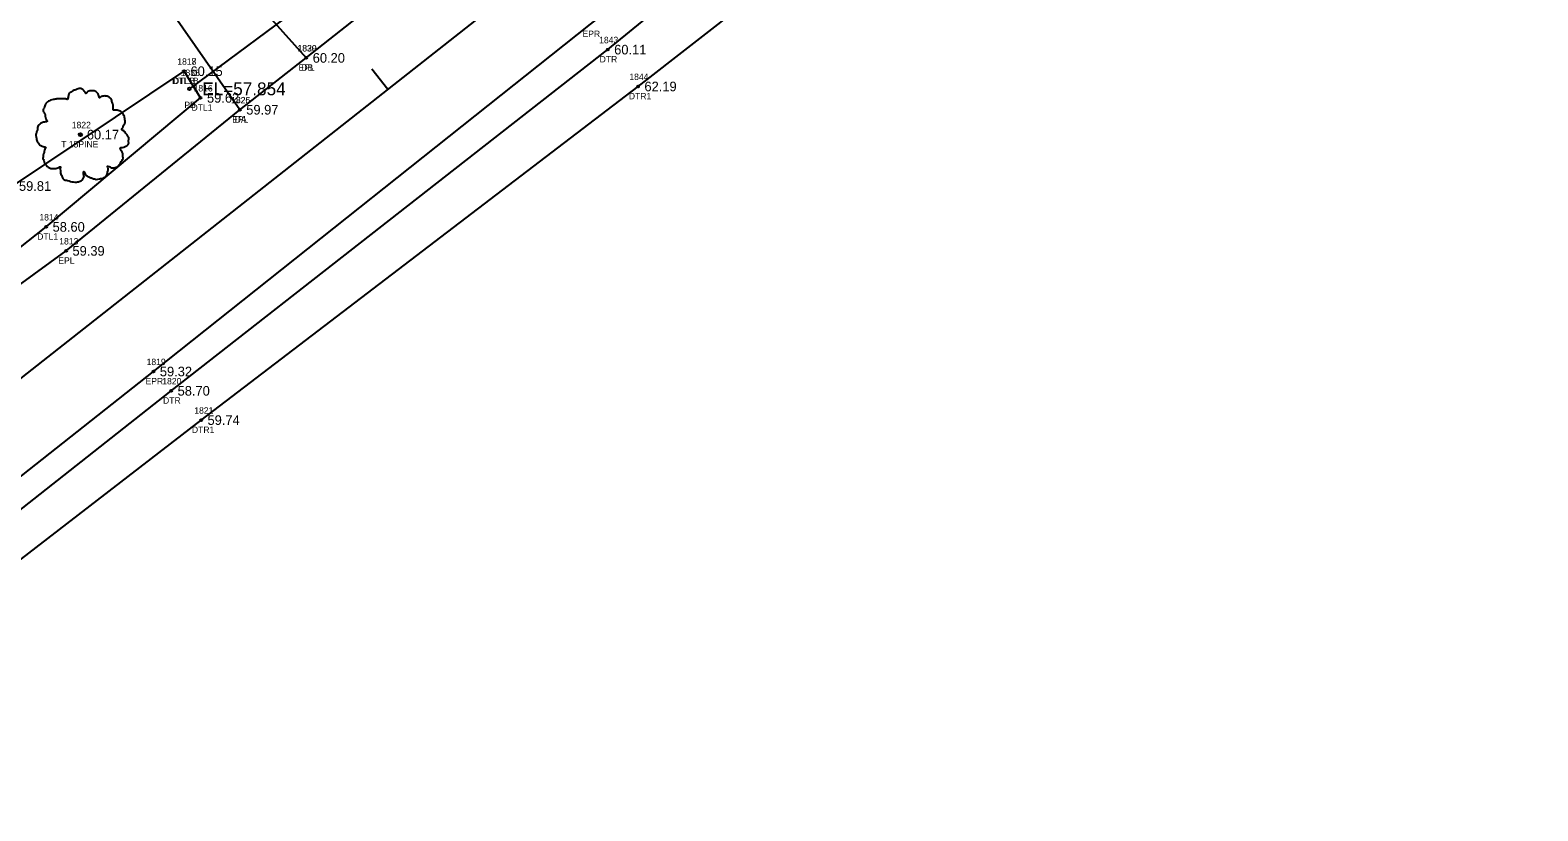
# Model space of a CAD drawing. Extents: x 2420113 to 2422887, y 845323 to 846653.
# Drawn here: x 2422429.8 to 2422664.8, y 846237.5 to 846359.2 of the extents above; entities that cross this region are included whole.
import ezdxf

# ---------------------------------------------------------------- set-up
doc = ezdxf.new("R2010")
doc.units = 0
for name, color, linetype in [('RD_EX_DR_Pipe', 7, 'Continuous'), ('RD_EX_DR_Pipe_txCode', 7, 'Continuous'), ('RD_EX_Driveway', 7, 'Continuous'), ('RD_EX_Driveway_txCode', 7, 'Continuous'), ('RD_EX_H2O', 7, 'Continuous'), ('RD_EX_H2O_txCode', 7, 'Continuous'), ('RD_EX_Road', 7, 'Continuous'), ('RD_EX_Road_txCode', 7, 'Continuous'), ('RD_EX_TX_Driveway_ELEV', 7, 'Continuous'), ('RD_EX_TX_H2O_ELEV', 7, 'Continuous'), ('RD_EX_TX_Road_ELEV', 7, 'Continuous'), ('RD_EX_TX_VEG_ELEV', 7, 'Continuous'), ('RD_EX_VEG', 7, 'Continuous'), ('RD_EX_VEG_txCode', 7, 'Continuous'), ('RD_HC_Cl', 7, 'Continuous'), ('RD_HC_Data_Tic', 7, 'Continuous'), ('RD_SMD_Locator', 7, 'Continuous'), ('RD_TX_Pipe_ElevEX', 7, 'Continuous')]:
    doc.layers.add(name, color=color, linetype=linetype)

msp = doc.modelspace()

# ---------------------------------------------------------------- linework, layer by layer
at = {"layer": 'RD_EX_DR_Pipe'}
msp.add_line((2422474.67, 846364.92), (2422454.62, 846350.03), dxfattribs=at)
at = {"layer": 'RD_EX_Driveway'}
for p, q in [((2422454.42, 846375.46), (2422472.85, 846354.85)), ((2422462.49, 846346.77), (2422449.78, 846364.98))]:
    msp.add_line(p, q, dxfattribs=at)
at = {"layer": 'RD_EX_H2O'}
for points in [[(2422383.12, 846248.84), (2422451.79, 846302.96), (2422519.84, 846356.14), (2422594.22, 846416.85), (2422660.96, 846466.59)], [(2422383.12, 846248.84), (2422386.53, 846244.46), (2422456.45, 846298.4), (2422524.56, 846350.4), (2422601.29, 846410.12), (2422664.82, 846461.69)], [(2422410.35, 846320.94), (2422427.06, 846334.88), (2422453.8, 846352.78)], [(2422410.35, 846320.94), (2422411.83, 846316.92), (2422415.48, 846315.23), (2422432.3, 846328.51), (2422456.37, 846348.62), (2422453.8, 846352.78)]]:
    msp.add_lwpolyline(points, dxfattribs=at)
at = {"layer": 'RD_EX_Road'}
for points in [[(2421810.77, 845819.82), (2421809.69, 845832.82), (2421803.88, 845842.86), (2421852.96, 845873.69), (2421939.48, 845935.12), (2421980.78, 845967.01), (2422140.12, 846092.81), (2422210.03, 846148.43), (2422282.88, 846205.21), (2422291.79, 846212.09), (2422354.49, 846261.98), (2422400.82, 846297.88), (2422417.34, 846311.65), (2422435.4, 846324.77), (2422462.49, 846346.77), (2422472.85, 846354.85), (2422502.3, 846378.16), (2422578.05, 846437.54), (2422605.64, 846459.09), (2422626.64, 846476.17), (2422642.61, 846488.86)], [(2421810.77, 845819.82), (2421865.31, 845853.52), (2421953.26, 845916.07), (2421995.06, 845948.03), (2422068.36, 846005.98), (2422153.46, 846073.36), (2422229.55, 846134.03), (2422245.4, 846145.63), (2422297.08, 846186.88), (2422369.77, 846243.69), (2422382.04, 846253.08), (2422449.02, 846305.97), (2422517.14, 846360.1), (2422592.58, 846419.1), (2422657.51, 846470.1)]]:
    msp.add_lwpolyline(points, dxfattribs=at)
at = {"layer": 'RD_EX_VEG'}
for centre, radius in [((2422437.64, 846342.89), 0.25), ((2422437.63, 846342.87), 0.0001)]:
    msp.add_circle(centre, radius, dxfattribs=at)
for points in [[(2422437.77, 846350.06), (2422437.47, 846350.08), (2422437.15, 846349.98), (2422436.9, 846349.88), (2422436.67, 846349.81), (2422436.45, 846349.71), (2422436.15, 846349.53), (2422435.92, 846349.33), (2422435.8, 846349.08), (2422435.75, 846348.86), (2422435.7, 846348.59), (2422435.7, 846348.41), (2422435.57, 846348.39), (2422435.42, 846348.41), (2422435.17, 846348.49), (2422434.92, 846348.49), (2422434.67, 846348.49), (2422434.32, 846348.46), (2422433.97, 846348.46), (2422433.7, 846348.41), (2422433.37, 846348.36), (2422433, 846348.24), (2422432.65, 846348.11), (2422432.35, 846347.86), (2422432.1, 846347.39), (2422431.97, 846347.04), (2422431.82, 846346.79), (2422431.97, 846346.34), (2422432.15, 846345.99), (2422432.17, 846345.79), (2422432.25, 846345.36), (2422432.35, 846345.14), (2422432.47, 846344.94), (2422432.4, 846344.91), (2422432.02, 846344.86), (2422431.72, 846344.76), (2422431.3, 846344.54), (2422431.07, 846344.31), (2422430.97, 846343.99), (2422430.95, 846343.64), (2422430.85, 846343.44), (2422430.77, 846343.16), (2422430.75, 846343.09), (2422430.7, 846342.76), (2422430.8, 846342.31), (2422430.82, 846341.96), (2422430.95, 846341.74), (2422431.1, 846341.56), (2422431.27, 846341.31), (2422431.67, 846341.09), (2422432, 846340.99), (2422432.2, 846340.96), (2422432.02, 846340.46), (2422431.97, 846340.11), (2422431.85, 846339.71), (2422431.85, 846339.64), (2422431.8, 846339.16), (2422431.95, 846338.84), (2422432.02, 846338.46), (2422432.2, 846338.24), (2422432.47, 846337.94), (2422432.8, 846337.71), (2422433.3, 846337.59), (2422433.7, 846337.61), (2422434.27, 846337.79), (2422434.52, 846337.86), (2422434.5, 846337.69), (2422434.52, 846337.31), (2422434.52, 846336.89), (2422434.67, 846336.57), (2422434.77, 846336.29), (2422434.92, 846336.04), (2422435.25, 846335.82), (2422435.65, 846335.74), (2422436.07, 846335.59), (2422436.52, 846335.52), (2422437.02, 846335.49), (2422437.62, 846335.64), (2422437.9, 846335.77), (2422438, 846335.94), (2422438.2, 846336.32), (2422438.15, 846336.54), (2422438.17, 846337.14), (2422438.27, 846336.97), (2422438.45, 846336.62), (2422438.95, 846336.32), (2422439.35, 846336.14), (2422439.82, 846335.99), (2422440.12, 846335.92), (2422440.6, 846335.99), (2422440.97, 846336.07), (2422441.35, 846336.19), (2422441.65, 846336.47), (2422441.82, 846336.74), (2422441.87, 846337.02), (2422441.94, 846337.39), (2422441.99, 846337.56)], [(2422441.99, 846337.56), (2422441.92, 846337.74), (2422441.87, 846337.99), (2422441.94, 846337.96), (2422442.12, 846337.91), (2422442.39, 846337.79), (2422442.62, 846337.71), (2422442.94, 846337.74), (2422443.22, 846337.84), (2422443.67, 846338.11), (2422443.94, 846338.59), (2422444.22, 846338.99), (2422444.29, 846339.31), (2422444.24, 846339.54), (2422444.22, 846340.04), (2422444.02, 846340.29), (2422443.97, 846340.41), (2422443.87, 846340.81), (2422443.94, 846340.86), (2422444.22, 846340.91), (2422444.59, 846341.04), (2422444.87, 846341.16), (2422445.09, 846341.34), (2422445.17, 846341.56), (2422445.14, 846341.96), (2422445.19, 846342.36), (2422445.12, 846342.51), (2422445.02, 846342.66), (2422444.94, 846342.86), (2422444.79, 846343.01), (2422444.69, 846343.16), (2422444.59, 846343.26), (2422444.47, 846343.41), (2422444.29, 846343.54), (2422444.14, 846343.59), (2422444.09, 846343.74), (2422444.24, 846343.94), (2422444.29, 846344.04), (2422444.32, 846344.26), (2422444.54, 846344.61), (2422444.59, 846345.01), (2422444.54, 846345.44), (2422444.49, 846345.71), (2422444.34, 846345.99), (2422444.14, 846346.24), (2422444.02, 846346.41), (2422443.84, 846346.54), (2422443.52, 846346.66), (2422443.27, 846346.71), (2422442.92, 846346.71), (2422442.72, 846346.76), (2422442.74, 846346.81), (2422442.74, 846346.96), (2422442.74, 846347.24), (2422442.67, 846347.69), (2422442.52, 846348.19), (2422442.52, 846348.21), (2422442.42, 846348.46), (2422442.19, 846348.66), (2422442.02, 846348.76), (2422441.82, 846348.88), (2422441.57, 846348.91), (2422441.27, 846348.91), (2422441, 846348.86), (2422440.8, 846348.76), (2422440.62, 846348.63), (2422440.55, 846348.78), (2422440.45, 846349.08), (2422440.4, 846349.23), (2422440.25, 846349.41), (2422440.02, 846349.61), (2422439.57, 846349.73), (2422438.95, 846349.66), (2422438.65, 846349.46), (2422438.5, 846349.28), (2422438.45, 846349.41), (2422438.25, 846349.61), (2422438.15, 846349.78), (2422437.97, 846349.91), (2422437.82, 846350.01), (2422437.72, 846350.06)]]:
    msp.add_spline(points, degree=3, dxfattribs=at)
at = {"layer": 'RD_HC_Cl'}
msp.add_line((2421944.32, 845923.85), (2422642.7, 846473.66), dxfattribs=at)
at = {"layer": 'RD_HC_Data_Tic'}
msp.add_line((2422485.55, 846349.94), (2422483.08, 846353.08), dxfattribs=at)
at = {"layer": 'RD_SMD_Locator'}
for centre, radius in [((2422519.84, 846356.14), 0.15), ((2422472.85, 846354.85), 0.15), ((2422472.85, 846354.85), 0.15), ((2422453.8, 846352.78), 0.15), ((2422453.8, 846352.78), 0.15), ((2422454.62, 846350.03), 0.2), ((2422456.37, 846348.62), 0.15), ((2422524.56, 846350.4), 0.15), ((2422462.49, 846346.77), 0.15), ((2422462.49, 846346.77), 0.15), ((2422437.64, 846342.89), 0.15), ((2422432.3, 846328.51), 0.15), ((2422435.4, 846324.77), 0.15), ((2422449.02, 846305.97), 0.15), ((2422451.79, 846302.96), 0.15), ((2422456.45, 846298.4), 0.15)]:
    msp.add_circle(centre, radius, dxfattribs=at)

# ---------------------------------------------------------------- texts
at = {"layer": 'RD_EX_DR_Pipe_txCode'}
for s, p in [('1835', (2422453.28, 846352.03)), ('PB', (2422453.84, 846347.03))]:
    msp.add_text(s, height=1, dxfattribs=at).set_placement(p)
at = {"layer": 'RD_EX_Driveway_txCode'}
for s, p in [('1829', (2422471.5, 846355.85)), ('DB', (2422472.07, 846352.85)), ('1826', (2422461.12, 846347.77)), ('DA', (2422461.7, 846344.77))]:
    msp.add_text(s, height=1, dxfattribs=at).set_placement(p)
at = {"layer": 'RD_EX_H2O_txCode'}
for s, p in [('1843', (2422518.5, 846357.14)), ('1817', (2422452.74, 846353.78)), ('1818', (2422452.74, 846353.78)), ('DTR', (2422518.57, 846354.14)), ('DTL1B', (2422451.92, 846350.78)), ('DTLB', (2422452.08, 846350.78)), ('1844', (2422523.21, 846351.4)), ('1816', (2422455.28, 846349.62)), ('DTR1', (2422523.13, 846348.4)), ('DTL1', (2422454.96, 846346.62)), ('1814', (2422431.24, 846329.51)), ('DTL1', (2422430.9, 846326.51)), ('1820', (2422450.4, 846303.96)), ('DTR', (2422450.52, 846300.96)), ('1821', (2422455.39, 846299.4)), ('DTR1', (2422455.02, 846296.4))]:
    msp.add_text(s, height=1, dxfattribs=at).set_placement(p)
at = {"layer": 'RD_EX_Road_txCode'}
for s, p in [('EPR', (2422515.91, 846358.1)), ('1830', (2422471.46, 846355.85)), ('EPL', (2422471.64, 846352.85)), ('1825', (2422461.15, 846347.77)), ('EPL', (2422461.29, 846344.77)), ('1813', (2422434.34, 846325.77)), ('EPL', (2422434.19, 846322.77)), ('1819', (2422447.96, 846306.97)), ('EPR', (2422447.79, 846303.97))]:
    msp.add_text(s, height=1, dxfattribs=at).set_placement(p)
at = {"layer": 'RD_EX_TX_Driveway_ELEV'}
for s, p in [('60.20', (2422473.85, 846354.1)), ('59.97', (2422463.49, 846346.02))]:
    msp.add_text(s, height=1.5, dxfattribs=at).set_placement(p)
at = {"layer": 'RD_EX_TX_H2O_ELEV'}
for s, p in [('60.11', (2422520.84, 846355.39)), ('60.15', (2422454.8, 846352.03)), ('60.15', (2422454.8, 846352.03)), ('62.19', (2422525.56, 846349.65)), ('59.62', (2422457.37, 846347.87)), ('59.81', (2422428.06, 846334.13)), ('58.60', (2422433.3, 846327.76)), ('58.70', (2422452.79, 846302.21)), ('59.74', (2422457.45, 846297.65))]:
    msp.add_text(s, height=1.5, dxfattribs=at).set_placement(p)
at = {"layer": 'RD_EX_TX_Road_ELEV'}
for s, p in [('60.20', (2422473.85, 846354.1)), ('59.97', (2422463.49, 846346.02)), ('59.39', (2422436.4, 846324.02)), ('59.32', (2422450.02, 846305.22))]:
    msp.add_text(s, height=1.5, dxfattribs=at).set_placement(p)
at = {"layer": 'RD_EX_TX_VEG_ELEV'}
msp.add_text('60.17', height=1.5, dxfattribs=at).set_placement((2422438.64, 846342.14))
at = {"layer": 'RD_EX_VEG_txCode'}
for s, p in [('1822', (2422436.29, 846343.89)), ('T 15PINE', (2422434.64, 846340.89))]:
    msp.add_text(s, height=1, dxfattribs=at).set_placement(p)
at = {"layer": 'RD_TX_Pipe_ElevEX'}
msp.add_text('EL=57.854', height=2, dxfattribs=at).set_placement((2422456.62, 846349.03))

doc.saveas('drawing.dxf')
